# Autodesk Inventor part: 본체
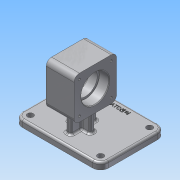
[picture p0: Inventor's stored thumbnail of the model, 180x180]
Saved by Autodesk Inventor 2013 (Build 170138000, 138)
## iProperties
Created: 2020-11
Part Number: 본체
Material: 알루미늄 6061
Document SubType Name: Modeling
Designer: user
Density: 2.71 g/cm^3
Mass: 681.977 g
Surface Area: 540.703 cm^2
Volume: 251.652 cm^3
Author: user
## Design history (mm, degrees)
sketch "스케치1"
  geometry: L1 (-37, 65)-(37, 65); L2 (49, 53)-(49, -53); L3 (37, -65)-(-37, -65); L4 (-49, -53)-(-49, 53); L5 (-49, 65)-(49, -65); L6 (49, 65)-(-49, -65); A1 r 12 centre (-37, 53) between (-37, 65) and (-49, 53); A2 r 12 centre (37, 53) between (49, 53) and (37, 65); A3 r 12 centre (37, -53) between (37, -65) and (49, -53); A4 r 12 centre (-37, -53) between (-49, -53) and (-37, -65); 1 further point
  constraints: 12 end point, 8 point on circle, 8 point on line, 8 tangent, 4 centre point, 2 equal radius, 2 midpoint, 2 parallel, 1 horizontal, 1 perpendicular
  dimensions: "d0" = 98 distance of L5.end L6.end; "d1" = 130 distance of L6.start L5.end; "d2" = 12 radius of A1; "d3" = 12 radius of A3
extrude "돌출1" new body sketch "스케치1" distance "d4" = 10; taper "d5" = 0 deg
node "작업 평면1"
sketch "스케치2"
  geometry: L1 (-12, 0)-(-12, 10) reference; L2 (-12, 10)-(86, 10) reference; L3 (86, 10)-(86, 0) reference; L4 (86, 0)-(-12, 0) reference; L5 (18, 102)-(82, 102); L6 (82, 102)-(82, 38); L7 (82, 38)-(18, 38); L8 (18, 38)-(18, 102); L9 (18, 102)-(82, 38); L10 (82, 102)-(18, 38); 2 further points
  constraints: 12 end point, 2 midpoint, 2 parallel, 1 horizontal, 1 perpendicular
  dimensions: "d6" = 64 distance of L6.end L7.end; "d7" = 64 distance of L5.end L6.end; "d9" = 70 distance from line of L4 point (50, 70); "d21" = 62 distance from line of L1 point (50, 70)
extrude "돌출2" join sketch "스케치2" stored distance "d10" = 42; taper "d11" = 0 deg
sketch "스케치3"
  geometry: L1 (-37, -65)-(37, -65) reference; L2 (49, -53)-(49, 53) reference; L3 (-49, -53)-(-49, 53) reference; L4 (-37, 65)-(37, 65) reference; L5 (49, 53)-(49, -53) reference; L6 (37, -65)-(-37, -65) reference; L7 (-9, -17)-(-17, -17); L8 (-17, -17)-(-17, 17); L9 (-17, 17)-(-9, 17); L10 (-9, 17)-(-9, -17); L11 (-9, -17)-(-17, 17); L12 (-17, -17)-(-9, 17); L13 (7, -4)-(-33, -4); L14 (-33, -4)-(-33, 4); L15 (-33, 4)-(7, 4); L16 (7, 4)-(7, -4); L17 (7, -4)-(-33, 4); L18 (-33, -4)-(7, 4); A1 r 12 centre (-37, -53) between (-49, -53) and (-37, -65) reference; A2 r 12 centre (-37, 53) between (-37, 65) and (-49, 53) reference; A3 r 12 centre (37, 53) between (49, 53) and (37, 65) reference; A4 r 12 centre (37, -53) between (37, -65) and (49, -53) reference; 4 further points
  constraints: 24 end point, 6 midpoint, 4 parallel, 2 horizontal, 2 perpendicular
  dimensions: "d12" = 8 distance of L8.end L9.end; "d13" = 34 distance of L7.end L8.end; "d14" = 65 distance from line of L1 point (-13, 0); "d15" = 62 distance from line of L2 point (-13, 0); "d16" = 40 distance of L14.end L15.end; "d17" = 8 distance of L13.end L14.end
extrude "돌출3" join sketch "스케치3" distance "d18" = 42; taper "d19" = 0 deg
node "작업 평면2"
sketch "스케치4"
  geometry: L1 (86, -28)-(86, -38) reference; L2 (86, -38)-(-44, -38) reference; L3 (-44, -38)-(-44, -28) reference; L4 (-44, -28)-(4, -28) reference; L5 (4, -28)-(4, 0) reference; L6 (4, 0)-(0, 0) reference; L7 (0, 0)-(0, 64) reference; L8 (0, 64)-(42, 64) reference; L9 (42, 64)-(42, 0) reference; L10 (42, 0)-(38, 0) reference; L11 (38, 0)-(38, -28) reference; L12 (38, -28)-(86, -28) reference; L13 (0, 53)-(14.7, 53); L14 (15, 52.7)-(15, 50); L15 (15, 50)-(27, 50); L16 (27, 50)-(27, 52.7); L17 (27.3, 53)-(42, 53); L18 (0, 53)-(0, 32); L19 (0, 32)-(42, 32); L20 (42, 32)-(42, 53); A1 r 0.3 centre (14.7, 52.7) between (15, 52.7) and (14.7, 53); A2 r 0.3 centre (27.3, 52.7) between (27.3, 53) and (27, 52.7); 3 further points
  constraints: 16 end point, 6 point on line, 4 point on circle, 4 tangent, 3 parallel, 2 centre point, 2 collinear, 2 midpoint, 1 equal radius, 1 perpendicular
  dimensions: "d22" = 15 distance of L13.start point (15, 53); "d24" = 15 distance of point (27, 53) L17.end; "d25" = 70 distance between parallel lines of L2 L19 (derived); "d26" = 42 diameter of L13 L19; "d27" = 42 diameter of L17 L19; "d28" = 36 diameter of L15 L19; "d29" = 0.3 radius of A1
revolve "회전1" sketch "스케치4" stored, may be unused: angle "d30" = 90 deg
sketch "스케치5"
  geometry: L1 (-82, 38)-(-82, 102) reference; L2 (-82, 102)-(-18, 102) reference; L3 (-18, 102)-(-18, 38) reference; L4 (-18, 38)-(-82, 38) reference; L5 (12, 10)-(12, 0) reference; L6 (12, 0)-(-86, 0) reference; L7 (-86, 0)-(-86, 10) reference; L8 (-86, 10)-(12, 10) reference; L9 (-74, 94)-(-26, 94); L10 (-26, 94)-(-26, 46); L11 (-26, 46)-(-74, 46); L12 (-74, 46)-(-74, 94); L13 (-74, 94)-(-26, 46); L14 (-26, 94)-(-74, 46); C1 r 21 at (-50, 70) reference; 5 further points
  constraints: 12 end point, 4 coincident, 2 midpoint, 2 parallel, 1 horizontal, 1 perpendicular
  dimensions: "d31" = 48 distance of L10.end L11.end; "d32" = 48 distance of L9.end L10.end
hole "구멍1" sketch "스케치5" at (-74, 94), (-74, 46), (-26, 46), (-26, 94) diameter "d33" = 3.242; stored, may be unused: countersink angle "d37" = 90 deg, drill point angle "d39" = 118 deg; dims "d34" = 8, "d35" = 4, "d36" = 2, "d38" = 10
sketch "스케치6"
  geometry: A1 r 12 centre (37, -53) between (37, -65) and (49, -53) reference; A2 r 12 centre (37, 53) between (49, 53) and (37, 65) reference; A3 r 12 centre (-37, 53) between (-37, 65) and (-49, 53) reference; A4 r 12 centre (-37, -53) between (-49, -53) and (-37, -65) reference; 1 further point
hole "구멍2" sketch "스케치6" at (-37, 53), (-37, -53), (37, -53), (37, 53) diameter "d40" = 9; stored, may be unused: countersink angle "d44" = 90 deg, drill point angle "d46" = 118 deg; dims "d41" = 8, "d42" = 4, "d43" = 2, "d45" = 10
fillet "모깎기1" dims "d47" = 8
chamfer "모따기1" distance "d48" = 1; stored, may be unused: second distance "d49" = 2, angle "d50" = 45 deg
fillet "모깎기2" dims "d51" = 3
fillet "모깎기3" dims "d52" = 3
fillet "모깎기4" dims "d53" = 3
sketch "스케치7"
  geometry: L1 (74.619, 9.595)-(74.619, -9.595); L2 (74.619, -9.595)-(3.381, -9.595); L3 (3.381, -9.595)-(3.381, 9.595); L4 (3.381, 9.595)-(74.619, 9.595); L5 (74.619, 0)-(3.381, 0); L6 (39, 9.595)-(39, -9.595); L7 (-37, -65)-(37, -65) reference; L8 (49, -53)-(49, 53) reference; L9 (37, 62)-(-37, 62) reference; L10 (-46, 53)-(-46, -53) reference; L11 (-37, -62)-(37, -62) reference; L12 (46, -53)-(46, 53) reference; L13 (-20, 14)-(-20, 7) reference; L14 (-20, 7)-(-30, 7) reference; L15 (-36, 1)-(-36, -1) reference; L16 (-30, -7)-(-20, -7) reference; L17 (-20, -7)-(-20, -14) reference; L18 (-14, -20)-(-12, -20) reference; L19 (-6, -14)-(-6, -7) reference; L20 (-6, -7)-(4, -7) reference; L21 (10, -1)-(10, 1) reference; L22 (4, 7)-(-6, 7) reference; L23 (-6, 7)-(-6, 14) reference; L24 (-12, 20)-(-14, 20) reference; C1 r 4.5 at (37, -53) reference; C2 r 4.5 at (-37, 53) reference; C3 r 4.5 at (-37, -53) reference; C4 r 4.5 at (37, 53) reference; A1 r 9 centre (37, 53) between (46, 53) and (37, 62) reference; A2 r 9 centre (-37, 53) between (-37, 62) and (-46, 53) reference; A3 r 9 centre (-37, -53) between (-46, -53) and (-37, -62) reference; A4 r 9 centre (37, -53) between (37, -62) and (46, -53) reference; A5 r 6 centre (-30, 1) between (-30, 7) and (-36, 1) reference; A6 r 6 centre (-30, -1) between (-36, -1) and (-30, -7) reference; A7 r 6 centre (-14, -14) between (-20, -14) and (-14, -20) reference; A8 r 6 centre (-12, -14) between (-12, -20) and (-6, -14) reference; A9 r 6 centre (4, -1) between (4, -7) and (10, -1) reference; A10 r 6 centre (4, 1) between (10, 1) and (4, 7) reference; A11 r 6 centre (-12, 14) between (-6, 14) and (-12, 20) reference; A12 r 6 centre (-14, 14) between (-14, 20) and (-20, 14) reference; 1 further point
  constraints: 4 end point, 4 midpoint, 2 other
  dimensions: "d54" = 65 distance between parallel lines of L5 L7; "d55" = 10 distance between parallel lines of L8 L6
feature "엠보싱1" sketch "스케치7" dims "d0" = 98, "d1" = 130, "d2" = 12, "d3" = 12, "d56" = 0.5, "d57" = 0
node "솔리드1"
mirror "대칭1"
node "절단 모서리 투영1"
node "절단 모서리 투영2"
node "절단 모서리 투영3"
node "절단 모서리 투영4"
node "절단 모서리 투영5"
